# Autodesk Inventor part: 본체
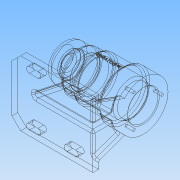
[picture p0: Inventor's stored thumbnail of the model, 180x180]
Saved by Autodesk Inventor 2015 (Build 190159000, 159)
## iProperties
Created: 2017-09
Part Number: 본체
Material: 일반
Document SubType Name: Modeling
Designer: owner
Density: 1 g/cm^3
Appearance: 기본값
Author: owner
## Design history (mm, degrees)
sketch "스케치3"
  geometry: L1 (0, 0)-(112, 0); L2 (112, 0)-(112, 34); L3 (112, 34)-(84, 34); L4 (84, 34)-(84, 30); L5 (84, 30)-(45, 30); L6 (45, 30)-(45, 27); L7 (45, 27)-(25, 27); L8 (25, 27)-(25, 25); L9 (25, 25)-(0, 25); L10 (0, 25)-(0, 0)
  constraints: 20 end point, 6 perpendicular, 2 horizontal, 2 vertical
  dimensions: "d5" = 112 distance of L1.start L1.end; "d6" = 25 distance between parallel lines of L8 L10; "d7" = 45 distance between parallel lines of L6 L10; "d9" = 84 distance between parallel lines of L4 L10; "d10" = 50 diameter of L9 L1; "d11" = 54 diameter of L7 L1; "d12" = 60 diameter of L5 L1; "d13" = 68 diameter of L3 L1
revolve "회전1" sketch "스케치3" stored, may be unused: angle "d14" = 90 deg
sketch "스케치4"
  geometry: L1 (112, -34)-(112, 34) reference; L2 (0, 0)-(112, 0); L3 (0, 0)-(0, -60); L4 (0, -60)-(22, -60); L5 (22, -60)-(38.077, 0); L6 (22, -60)-(84.117, -60); L7 (38.077, 0)-(112, 0); L8 (112, 0)-(112, -60); L9 (22, -60)-(112, -60); L10 (112, -60)-(112, -62)
  constraints: 18 end point, 3 horizontal, 3 vertical, 2 midpoint, 1 equal length, 1 perpendicular
  dimensions: "d15" = 60 distance of L2.start L3.end; "d16" = 22 distance of L3.end L4.end; "d17" = 75 deg angle of L6 L5; "d18" = 60 distance of L7.end L8.end; "d100" = 2 distance of L8.end L10.end
extrude "돌출1" join sketch "스케치4" stored distance "d19" = 8; taper "d20" = 0 deg
sketch "스케치5"
  geometry: L1 (0, 0)-(0, 26.236) reference; L2 (8, 0)-(0, 0) reference; L3 (8, 26.236)-(8, 0) reference; L4 (4, 26)-(4, 0); L5 (4, 0)-(4, -2); L6 (4, -2)-(39, -2); L7 (39, -2)-(25.9, 33.992); A1 r 34 centre (4, 60) between (8, 26.236) and (0, 26.236) reference; A2 r 34 centre (4, 60) between (4, 26) and (25.9, 33.992)
  constraints: 9 end point, 2 point on circle, 1 centre point, 1 coincident, 1 horizontal, 1 midpoint, 1 parallel, 1 vertical
  dimensions: "d21" = 60 distance of A1.centre L4.end; "d24" = 34 radius of A2; "d97" = 2 distance of L4.end L5.end; "d98" = 35 distance of L5.end L6.end; "d99" = 110 deg angle of L6 L7
extrude "돌출2" join sketch "스케치5" distance "d26" = 8; taper "d27" = 0 deg
sketch "스케치9"
  geometry: C1 r 21 at (0, 0); A1 r 34 centre (0, 0) between (21.9, -26.008) and (-21.9, -26.008) reference; 2 further points
  constraints: 1 centre point, 1 coincident
  dimensions: "d34" = 42 diameter of C1
extrude "돌출4" cut sketch "스케치9" distance "d35" = 15; taper "d36" = 0 deg
sketch "스케치12"
  geometry: C1 r 21 at (0, 0) reference; C2 r 24 at (0, 0)
  constraints: 1 centre point, 1 coincident
  dimensions: "d41" = 48 diameter of C2
extrude "돌출6" cut sketch "스케치12" distance "d42" = 54; taper "d43" = 0 deg
sketch "스케치13"
  geometry: C1 r 24 at (0, 0) reference; C2 r 21 at (0, 0)
  constraints: 1 centre point, 1 coincident
  dimensions: "d44" = 42 diameter of C2
extrude "돌출7" cut sketch "스케치13" distance "d45" = 12; taper "d46" = 0 deg
sketch "스케치14"
  geometry: C1 r 21 at (0, 0) reference; C2 r 17.5 at (0, 0)
  constraints: 1 centre point, 1 coincident
  dimensions: "d47" = 35 diameter of C2
extrude "돌출8" cut sketch "스케치14" distance "d48" = 18; taper "d49" = 0 deg
sketch "스케치15"
  geometry: C1 r 17.5 at (0, 0) reference; C2 r 16 at (0, 0)
  constraints: 1 centre point, 1 coincident
  dimensions: "d50" = 32 diameter of C2
extrude "돌출9" cut sketch "스케치15" distance "d51" = 4; taper "d52" = 0 deg
sketch "스케치16"
  geometry: C1 r 16 at (0, 0) reference; C2 r 10.5 at (0, 0)
  constraints: 1 centre point, 1 coincident
  dimensions: "d53" = 21 diameter of C2
extrude "돌출10" cut sketch "스케치16" distance "d54" = 3; taper "d55" = 0 deg
node "작업 평면3"
sketch "스케치21"
  geometry: L1 (47.5, 21)-(47.5, -21) reference; 2 further points
  constraints: 1 other
  dimensions: "d71" = 0 vertical distance of point (-0.5, 0) point (-64.5, 0); "d72" = 48 distance from line of L1 point (-0.5, 0)
feature "엠보싱1" sketch "스케치21" dims "d5" = 112, "d6" = 25, "d7" = 45, "d9" = 84, "d10" = 50, "d11" = 54, "d12" = 60, "d13" = 68, "d73" = 0.5, "d74" = 0
sketch "스케치22" dims "d75" = 52
  geometry: L1 (0, 0)-(0, 26); A1 r 34 centre (0, 0) between (21.9, -26.008) and (-21.9, -26.008) reference; 3 further points
  constraints: 2 coincident, 2 end point, 1 vertical, 1 vertical alignment, 2 other
hole "구멍1" sketch "스케치22" at (0, 26) diameter "d76" = 3.242; stored, may be unused: countersink angle "d80" = 90 deg, drill point angle "d82" = 118 deg; dims "d77" = 8, "d78" = 4, "d79" = 2, "d81" = 11
chamfer "모따기1" distance "d86" = 1; stored, may be unused: second distance "d87" = 2, angle "d88" = 45 deg
fillet "모깎기1" dims "d92" = 0.3
fillet "모깎기2" dims "d93" = 9
fillet "모깎기3" dims "d94" = 3
fillet "모깎기4" dims "d95" = 3
fillet "모깎기5" dims "d96" = 3
sketch "스케치24"
  geometry: L1 (75.894, 0)-(0, 0) reference; L2 (78.894, 11)-(78.894, -3) reference; L3 (0, 8)-(75.894, 8) reference; L4 (-3.106, 5)-(-3.106, 3) reference; L5 (78.894, 4)-(78.894, 8); L6 (78.894, 8)-(-3.106, 8); L7 (-3.106, 4)-(-3.106, 8); L8 (-3.106, 4)-(-3.106, 0); L9 (-3.106, 0)-(78.894, 0); L10 (78.894, 0)-(78.894, 8); A1 r 3 centre (75.894, -3) between (78.894, -3) and (75.894, 0) reference; A2 r 3 centre (75.894, 11) between (75.894, 8) and (78.894, 11) reference; 3 further points; 2 other entities
  constraints: 12 end point, 3 vertical, 2 midpoint, 2 perpendicular, 2 point on line, 2 other
  dimensions: "d101" = 4 distance of L5.start L5.end; "d102" = 4 distance of L7.start L8.end
extrude "돌출12" join sketch "스케치24" distance "d103" = 2; taper "d104" = 0 deg
fillet "모깎기6" dims "d105" = 3
sketch "스케치25"
  geometry: L1 (8, 70)-(8, 0) reference; L2 (8, 35)-(8, 80); L3 (8, 80)-(-104, 80); L4 (-104, 80)-(-104, -10); L5 (-104, -10)-(8, -10); L6 (8, -10)-(8, 35); 1 further point
  constraints: 10 end point, 2 perpendicular, 1 collinear, 1 midpoint, 1 point on line, 1 vertical
  dimensions: "d106" = 45 distance of L2.start L2.end; "d107" = 112 distance of L2.end L3.end; "d108" = 90 distance of L3.end L4.end; "d109" = 112 distance of L4.end L5.end
extrude "돌출13" join sketch "스케치25" distance "d110" = 8; taper "d111" = 0 deg
sketch "스케치27"
  geometry: L1 (8, -70)-(8, -80) reference; L2 (-28, -69)-(-16, -69); L3 (-28, -73)-(-16, -73); L4 (-16, -65)-(-28, -65); A1 r 4 centre (-28, -69) between (-28, -65) and (-28, -73); A2 r 4 centre (-16, -69) between (-16, -73) and (-16, -65); 2 further points
  constraints: 8 end point, 4 point on circle, 4 tangent, 2 centre point, 1 horizontal, 1 midpoint, 1 parallel
  dimensions: "d112" = 6 distance of point (-22, -69) L2.end; "d113" = 8 diameter of A2; "d114" = 34 distance from line of L2 point (-104, -35); "d115" = 24 distance from line of L1 L2.end
extrude "돌출14" cut sketch "스케치27" stored distance "d116" = 8; taper "d117" = 0 deg
chamfer "모따기3" distance "d121" = 12; stored, may be unused: second distance "d122" = 2, angle "d123" = 45 deg
fillet "모깎기8" dims "d125" = 3
fillet "모깎기9" dims "d126" = 3
fillet "모깎기10" dims "d127" = 3
fillet "모깎기11" dims "d129" = 3
node "솔리드1"
mirror "대칭1"
pattern_circular "원형 패턴1" dims angle "d84" = 360 deg
pattern_linear "직사각형 패턴3" dims "d120" = 52
mirror "대칭3"
node "작업 평면1"
node "작업 평면4"
